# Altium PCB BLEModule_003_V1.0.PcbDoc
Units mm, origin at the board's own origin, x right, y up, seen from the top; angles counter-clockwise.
Board outline 13.5 x 21.9 mm, 2 copper layers (TopLayer, BottomLayer); 12 components, 12 nets, 54 pads, 24 vias.
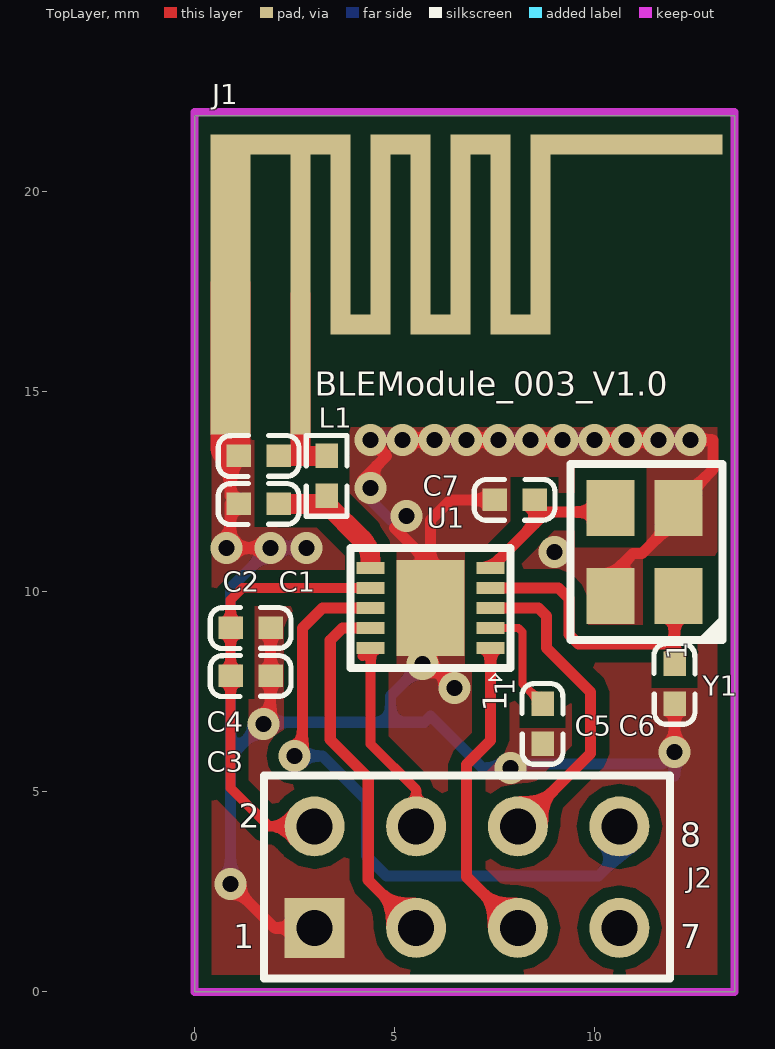
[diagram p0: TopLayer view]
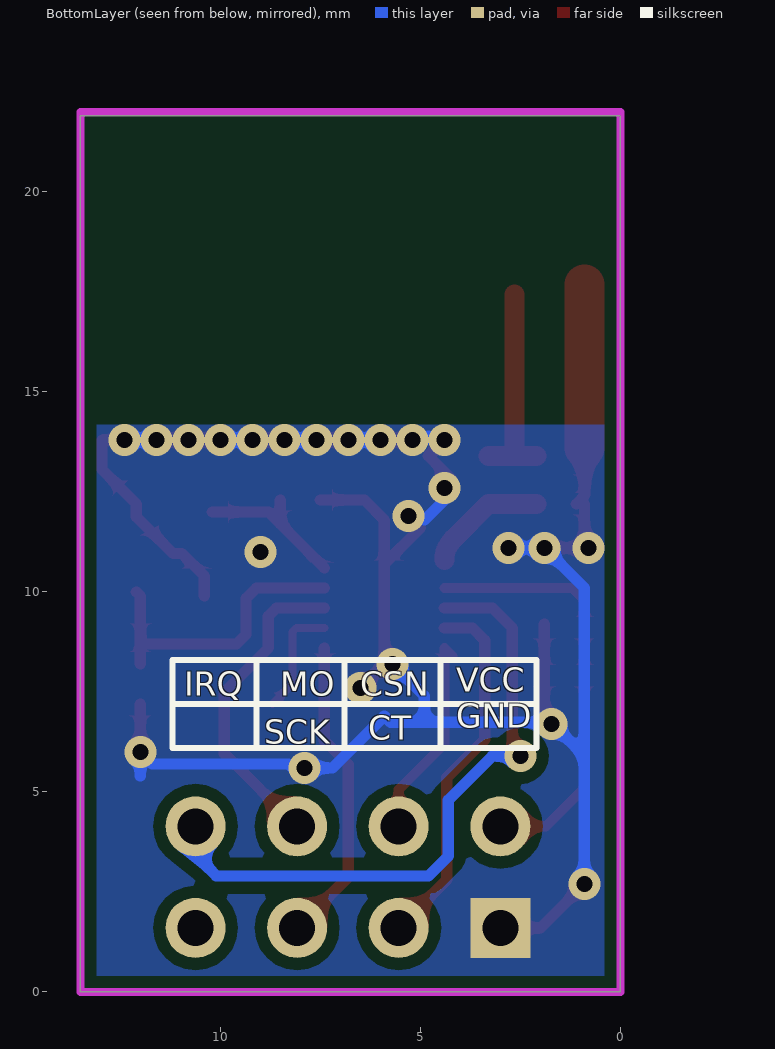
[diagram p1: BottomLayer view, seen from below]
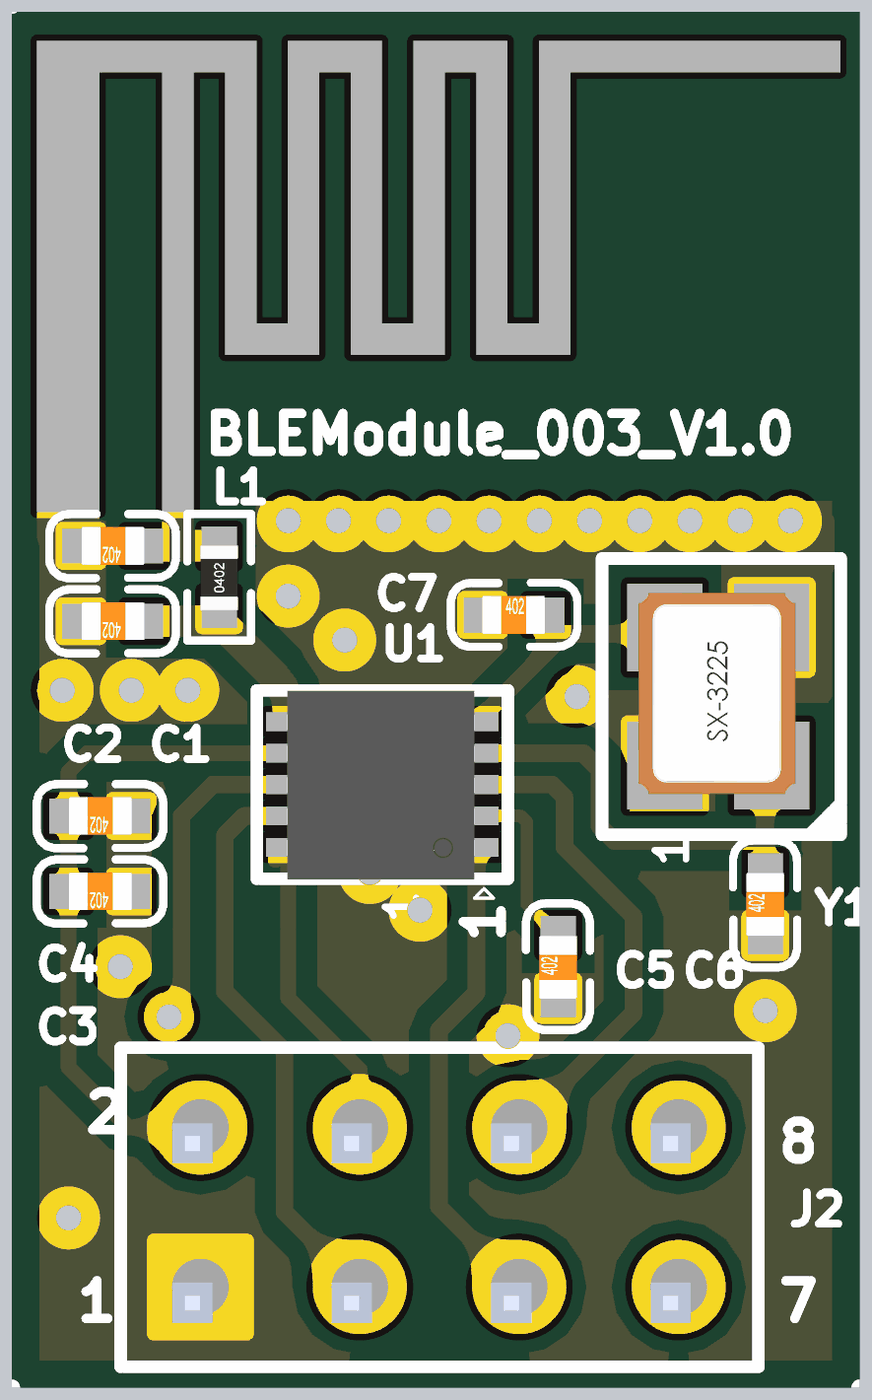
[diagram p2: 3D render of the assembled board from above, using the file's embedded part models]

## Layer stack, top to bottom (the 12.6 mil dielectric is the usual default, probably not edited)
TopSolder: solder mask 0.0102, Solder Resist, Dk 3.5
TopLayer: signal copper 0.0356
Dielectric1: dielectric 0.32, FR-4, Dk 4.8
BottomLayer: signal copper 0.0356
BottomSolder: solder mask 0.0102, Solder Resist, Dk 3.5

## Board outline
0,0 13.5,0 13.5,21.9 0,21.9

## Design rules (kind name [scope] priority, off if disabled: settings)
Clearance [All] p1: gap=0.3
PlaneConnect [All] p1: planeconnectstyle=Direct reliefexpansion=0.508 reliefentries=4 reliefconductorwidth=0.254 reliefairgap=0.254
PolygonConnect PolygonConnect_7 [All vs IsNamedPolygon('GND_L01_P016')] p1: connectstyle=Direct reliefconductorwidth=0.254 reliefentries=4 polygonreliefangle="90 Angle" airgapwidth=0.254
PolygonConnect PolygonConnect_6 [All vs IsNamedPolygon('GND_L02_P018')] p2: connectstyle=Direct reliefconductorwidth=0.254 reliefentries=4 polygonreliefangle="90 Angle" airgapwidth=0.254
PolygonConnect PolygonConnect_5 [All vs IsNamedPolygon('GND_L01_P016')] p3: connectstyle=Direct reliefconductorwidth=0.254 reliefentries=4 polygonreliefangle="90 Angle" airgapwidth=0.254
PolygonConnect PolygonConnect_4 [All vs IsNamedPolygon('GND_L02_P014')] p4: connectstyle=Direct reliefconductorwidth=0.254 reliefentries=4 polygonreliefangle="90 Angle" airgapwidth=0.254
PolygonConnect PolygonConnect_3 [All vs IsNamedPolygon('GND_L01_P012')] p5: connectstyle=Direct reliefconductorwidth=0.254 reliefentries=4 polygonreliefangle="90 Angle" airgapwidth=0.254
PolygonConnect PolygonConnect_2 [All vs IsNamedPolygon('GND_L01_P012')] p6: connectstyle=Direct reliefconductorwidth=0.254 reliefentries=4 polygonreliefangle="90 Angle" airgapwidth=0.254
PolygonConnect PolygonConnect_1 [All vs IsNamedPolygon('GND_L02_P014')] p7: connectstyle=Direct reliefconductorwidth=0.254 reliefentries=4 polygonreliefangle="90 Angle" airgapwidth=0.254
PolygonConnect [All] p8: connectstyle=Relief reliefconductorwidth=0.254 reliefentries=4 polygonreliefangle="90 Angle" airgapwidth=0.254
RoomDefinition BLEModule_003_V1.0 [InComponentClass('BLEModule_003_V1.0')] p1: confinementstyle=ConfineIn formatcopy=TRUE lockcomponents=FALSE outline -1147.202,-1294.416 -1096.402,-1294.416 -1096.402,-1269.016 -1147.202,-1269.016
RoutingVias [All] p1: holewidth=0.4 width=0.8 viastyle="Through Hole" minholewidth=0.3 minwidth=0.6 maxholewidth=0.4 maxwidth=0.8
SolderMaskExpansion [All] p1: expansion=0.102
Width [All] p1: maxlimit=1 minlimit=0.2 preferedwidth=0.25
29 further rules are at their usual default settings.

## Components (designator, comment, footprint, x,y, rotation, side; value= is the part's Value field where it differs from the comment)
C1 "1.2pF" 0402C 1.1,12.2 r180 top
C2 "6.8pF" 0402C 1.1,13.4 r180 top
C3 "1uF" 0402C 0.9,7.9 r180 top
C4 "0.1uF" 0402C 0.9,9.1 r180 top
C5 "1uF" 0402C 8.7,7.2 r90 top
C6 "15pF" 0402C 12,8.2 r90 top
C7 "15pF" 0402C 8.5,12.3 r0 top
J1 "ANTENNA--F" PIFA_LARGE 0.4,14 r0 top
J2 "2x5" HDR2X4 3,1.6 r0 top
L1 "3.6nF" 0402 3.3,13.4 r90 top
U1 "BLE_MG127" DFN10 7.4,8.6 r90 top
Y1 "16MHz" XT3225 12.5,9.4 r90 top

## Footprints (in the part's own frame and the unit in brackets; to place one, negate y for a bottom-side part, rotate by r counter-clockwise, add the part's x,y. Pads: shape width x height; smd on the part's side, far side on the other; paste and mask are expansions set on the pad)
0402 [mil]
  rect 24x22 smd: 1(0,0) 2(-39.37,0)
  silkscreen extent -59,-20 20,20, body extent -40,-12 0,12, height 13
0402C [mil]
  rect 24x22 smd: 1(0,0) 2(-39.37,0)
  silkscreen extent -59,-20 20,20, body extent -40,-12 0,12, height 8
DFN10 [mm]
  rect 2.4x1.7 smd: 0(0.999,1.499)
  rect 0.3x0.7 smd: 1(0,0) 2(0.5,0) 3(1,0) 4(1.5,0) 5(2,0) 6(2,3) 7(1.5,3) 8(1,3) 9(0.5,3) 10(0,3)
  silkscreen extent -0.81,-0.5 2.5,3.5, body extent -0.51,0.02 2.49,3.02, height 0.8
HDR2X4 [mm] "Connector; Header; 4x2 Position"
  rect 1.5x1.5 hole 0.9: 1(0,0)
  round 1.5 hole 0.9: 2(0,2.54) 3(2.54,0) 4(2.54,2.54) 5(5.08,0) 6(5.08,2.54) 7(7.62,0) 8(7.62,2.54)
  silkscreen extent -1.27,-1.27 8.89,3.81, body extent -1.4,-1.52 8.76,3.56, height 2.8
PIFA_LARGE [mm]
  rect 0.5x7 smd: 1(2.244,3.44)
  rect 1x7.5 smd: 2(0.494,3.69)
  rect 3x0.5 smd: ""(1.994,7.19)
  rect 0.5x5 smd: ""(3.244,4.94) ""(4.244,4.94) ""(5.244,4.94) ""(6.244,4.94) ""(7.244,4.94) ""(8.244,4.94)
  rect 1x0.5 smd: ""(3.744,2.69) ""(4.744,7.19) ""(5.744,2.69) ""(6.744,7.19) ""(7.744,2.69)
  rect 4.3x0.5 smd: ""(10.644,7.19)
XT3225 [mm]
  rect 1.4x1.2 smd: 1(0.5,0.4) 2(2.7,0.4) 3(2.7,2.1) 4(0.5,2.1)
  silkscreen extent -0.6,-0.7 3.8,3.1, body extent -0.1,-0.1 3.3,2.6, height 0.81

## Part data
C1 C2 C3 C4 C5 C6 C7: library part CAP, "Capacitor"
J1: library part ANT
J2: library part "Header 4X2", "Header, 4-Pin, Dual row"
L1: library part Res2, "Resistor"
Y1: library part XTAL3225

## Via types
v1: diameter 0.8, hole 0.4, TopLayer to BottomLayer, 24 vias

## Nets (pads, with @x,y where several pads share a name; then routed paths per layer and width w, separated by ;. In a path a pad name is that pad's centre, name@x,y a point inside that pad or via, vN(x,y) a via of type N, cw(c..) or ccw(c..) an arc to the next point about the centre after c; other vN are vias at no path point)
ANT: C1.2 L1.2 U1.6 | length 3
  TopLayer w0.5: C1.2 3.3,12.2 4.18,11.32 ; 4.18,11.319 4.18,11.315 4.191,11.304 cw(c3.688,10.8) 4.4,10.8
CSN: J2.4 U1.10 | length 5.2
  TopLayer w0.25: 4.2,8.4 U1.10 4.4,6.2 5.54,5.06 J2.4
CT: J2.3 U1.9 | length 9.2
  TopLayer w0.28: U1.9 3.7,9.1 3.39,8.79 3.39,6.31 4.34,5.36 4.34,2.8 J2.3
GND: C1.1 C2.1 C3.2 C4.2 C5.2 C6.2 C7.2 J1.2 J2.1 U1.0 Y1.2 Y1.4 | length 63.6
  TopLayer w0.28: C1.1@0.894,12.2 0.894,11.406 1.2,11.1 v1(1.9,11.1) ; C2.1@0.894,13.604 0.894,12.406 C1.1 ; v1(0.9,2.7) 2,1.6 J2.1 ; v1(1.725,6.7) 1.9,6.875 C4.2@1.9,9.2 ; v1(4.4,12.6) 4.2,12.8 4.8,13.4 v1(4.4,13.8) ; v1(5.2,13.8) v1(6,13.8) ; v1(5.3,11.9) 5,11.6 U1.0@5.901,10.699 ; v1(5.7,8.2) 5.9,8.2 v1(6.5,7.6) ; v1@5.901,8.2 U1.0 U1.0@5.901,10.699 ; v1(6.8,13.8) v1(7.6,13.8) ; C7.2 6.4,12.3 5.901,11.801 U1.0@5.901,10.699 ; v1(8.4,13.8) v1(9.2,13.8) ; v1(10,13.8) v1(10.8,13.8) v1(11.6,13.8) ; Y1.4 10.4,10.4 10.96,10.96 11.182,10.96 12.1,11.878 Y1.2 12.1,12.2 12.96,13.06 12.96,13.8 v1(12.4,13.8) ; v1(12,6) C6.2
  TopLayer w1: C2.1@0.894,13.604 J1.2
  BottomLayer w0.28: v1(0.9,2.7) 0.9,5.9 ; v1(2.8,11.1) v1(1.9,11.1) 0.9,10.1 0.9,5.9 ; v1(4.4,12.6) 4.4,12.3 4.9,11.8 5,11.9 v1(5.3,11.9) ; v1(4.4,13.8) 4.7,13.8 4.8,13.9 4.9,13.8 v1(5.2,13.8) ; v1(5.7,8.2) 4.9,7.4 4.9,6.74 ; v1(6,13.8) v1(6.8,13.8) ; v1(7.6,13.8) v1(8.4,13.8) ; v1(9.2,13.8) v1(10,13.8) ; v1@11.7,13.9 v1(11.6,13.8) v1(12.4,13.8) ; 12,5.4 v1(12,6) 11.7,5.7 8.3,5.7 8,5.4 7.9,5.5 v1(7.9,5.6) 7.2,5.6 5.9,6.9 5.74,6.74 4.9,6.74 ; 0.9,5.9 1.7,6.7 v1(1.725,6.7) 1.765,6.74 4.9,6.74
  other v1: 9,11 0.8,11.1
IRQ: J2.8 U1.8 | length 16.3
  TopLayer w0.28: v1(2.5,5.9) 2.7,6.1 2.7,9.1 3.2,9.6 U1.8
  BottomLayer w0.28: v1(2.5,5.9) 3.2,5.9 4.3,4.8 4.3,3.4 4.8,2.9 10.1,2.9 10.62,3.42 J2.8
MOSI: J2.6 U1.3 | length 8
  TopLayer w0.28: U1.3 8.6,9.6 8.8,9.4 8.8,8.6 9.9,7.5 9.9,5.96 J2.6
NetC2_2: C2.2 J1.1 L1.1 | length 5.2
  TopLayer w0.5: C2.2 2.644,13.4 ; J1.1 2.644,13.4 ; L1.1 2.644,13.4
NetC5_1: C5.1 U1.2 | length 2.8
  TopLayer w0.2: U1.2 8.1,9.1 8.2,9 8.2,7.7 C5.1
NetC6_1: C6.1 U1.4 Y1.1 | length 7.6
  TopLayer w0.28: U1.4 9.1,10.1 9.36,9.84 9.36,8.94 9.6,8.7 11.9,8.7 12,8.8 ; C6.1 12,8.8 ; Y1.1@12.1,10 12,9.9 12,8.8
NetC7_1: C7.1 U1.5 Y1.3 | length 4
  TopLayer w0.28: U1.5 8.5,11.7 ; C7.1 8.5,11.7 ; Y1.3@10.2,12 8.8,12 8.5,11.7
SCK: J2.5 U1.1 | length 7.8
  TopLayer w0.28: U1.1 7.4,6.288 6.8,5.688 6.8,2.88 J2.5
VCC_3V: C3.1 C4.1 J2.2 U1.7 | length 10.8
  TopLayer w0.25: J2.2 1.86,4.14 0.9,5.1 0.9,8 0.9,9.2 0.9,9.8 1.2,10.1 U1.7
pads on no net: J1. J2.7
copper on no net: | length 3.7
  TopLayer w0.28: 0.894,17.69 1,17.584 1,14.08

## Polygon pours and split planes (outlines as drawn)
GND on TopLayer "GND_L01_P016" (solid, remove dead copper, pour order 16): 0.205,14.121 13.405,14.121 13.405,-0.079 0.105,-0.079 0.105,14.021 0.205,14.121
GND on BottomLayer "GND_L02_P018" (solid, remove dead copper, pour order 18): 0.083,14.183 13.383,14.183 13.383,-0.017 0.083,-0.017 0.083,14.183

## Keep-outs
KeepOutLayer:
  lines w0.2: 0,0 0,22 13.5,22 13.5,0 0,0

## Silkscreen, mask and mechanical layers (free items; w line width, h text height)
TopOverlay:
  text "BLEModule_003_V1.0" at 3,14.9 h0.6
  text "1" at 7.8,7 h0.6 r90
BottomOverlay:
  lines w0.15: 2.1,7.2 4.5,7.2 11.2,7.2 ; 4.5,6.1 4.5,8.3 ; 6.9,6.1 6.9,8.3 ; 9.1,6.1 9.1,8.3 ; 2.1,6.1 11.2,6.1 11.2,8.3 2.1,8.3 2.1,6.1
  text "VCC" at 4.1,7.5 h0.6
  text "CSN" at 6.5,7.4 h0.6
  text "MO" at 8.5,7.4 h0.6
  text "IRQ" at 10.9,7.4 h0.6
  text "GND" at 4.1,6.6 h0.6
  text "CT" at 6.3,6.3 h0.6
  text "SCK" at 8.9,6.2 h0.6

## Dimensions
0,22 to 0,0 on TopOverlay
0,0 to 13.5,0 on TopOverlay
